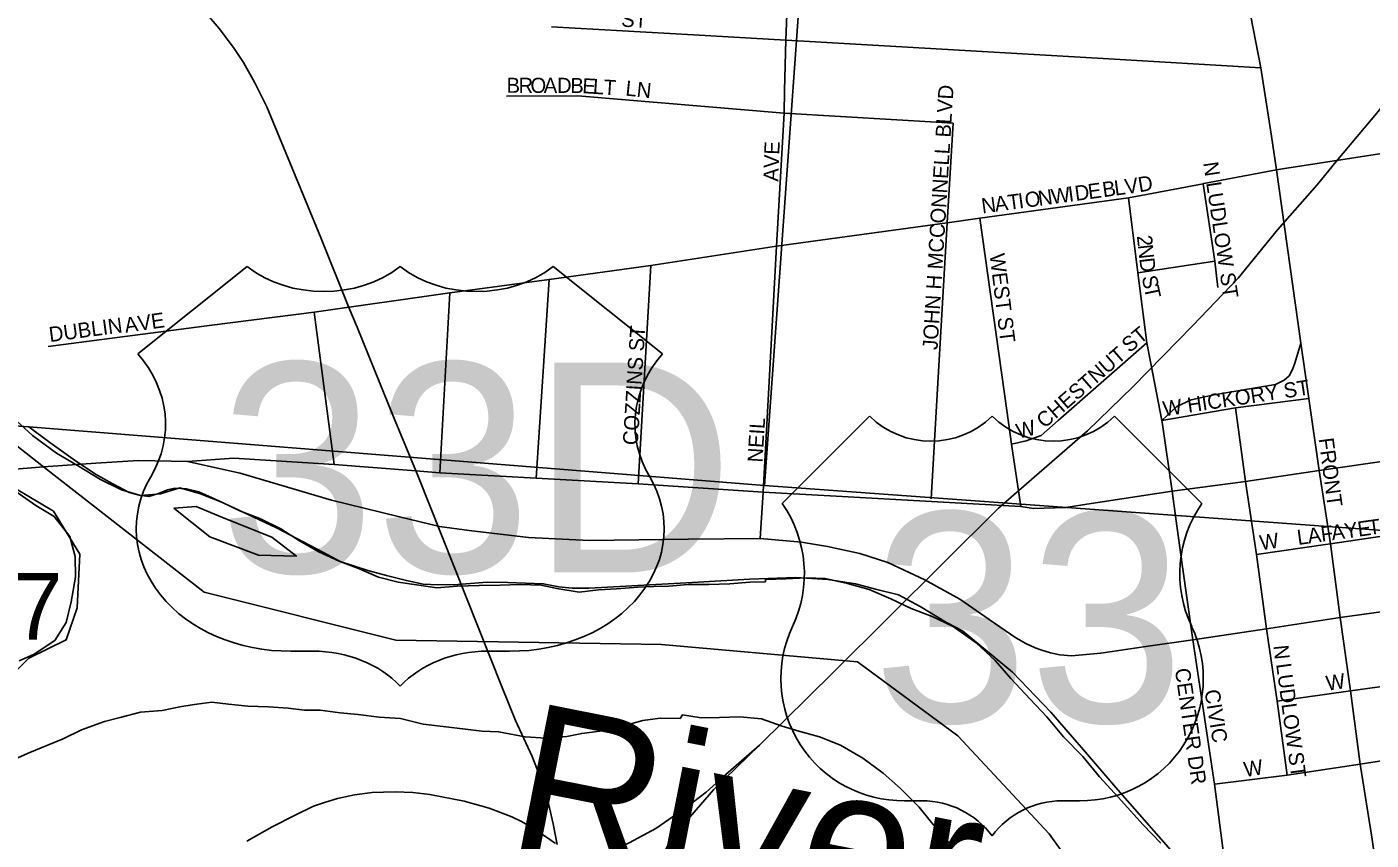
# Model space of a CAD drawing. Extents: x 0 to 34, y -6.2 to 22.
# Drawn here: x 5.72 to 6.564, y 18.089 to 18.6 of the extents above; entities that cross this region are included whole.
import ezdxf

# ---------------------------------------------------------------- set-up
doc = ezdxf.new("R2010")
doc.units = 0
for name, color, linetype in [('GM_X_City_Street', 7, 'Continuous'), ('GM_X_City_Street_Text', 7, 'Continuous'), ('GM_X_Major_River', 7, 'Continuous'), ('GM_X_Major_River_Text', 7, 'Continuous'), ('GM_X_Rail_Line', 7, 'Continuous'), ('GM_X_Section', 7, 'Continuous'), ('GM_X_Section_Text', 7, 'Continuous'), ('GM_X_Township', 7, 'Continuous'), ('GM_X_US_Route', 7, 'Continuous'), ('GM_X_US_Shield', 7, 'Continuous')]:
    doc.layers.add(name, color=color, linetype=linetype)

msp = doc.modelspace()

# ---------------------------------------------------------------- linework, layer by layer
at = {"layer": 'GM_X_City_Street'}
for points in [[(6.19591, 18.56034), (6.19665, 18.59208), (6.20072, 18.6952), (6.20307, 18.75671), (6.20288, 18.76478), (6.1973, 18.78643), (6.19155, 18.79843), (6.17255, 18.82567), (6.16294, 18.83821), (6.15118, 18.86085), (6.1493, 18.86763), (6.13803, 18.94558), (6.12654, 19.0265), (6.11342, 19.1096), (6.10394, 19.17992), (6.09467, 19.24481), (6.08497, 19.31221), (6.07265, 19.3982), (6.06886, 19.42877), (6.06015, 19.48517), (6.05243, 19.53925), (6.03434, 19.65927), (6.03319, 19.66897), (6.01654, 19.78521)], [(6.57176, 18.04339), (6.56472, 18.09113), (6.55749, 18.13701), (6.5515, 18.18306), (6.54503, 18.22919), (6.5388, 18.27541), (6.53176, 18.32162), (6.52531, 18.3669), (6.52024, 18.40154), (6.50489, 18.51058), (6.5018, 18.5316), (6.49515, 18.57457), (6.48857, 18.60785), (6.46909, 18.66011)], [(6.04941, 18.60033), (6.13856, 18.59533)], [(6.13856, 18.59533), (6.19665, 18.59208), (6.20791, 18.59142)], [(6.20791, 18.59142), (6.3961, 18.58038)], [(6.3961, 18.58038), (6.49515, 18.57457)], [(6.02127, 18.5569), (6.06604, 18.55692), (6.19557, 18.54604), (6.30173, 18.53987)], [(6.18061, 18.27874), (6.18232, 18.308), (6.19087, 18.46253), (6.19557, 18.54604), (6.19591, 18.56034)], [(6.29792, 18.47709), (6.30173, 18.53987)], [(6.5087, 18.51116), (6.5981, 18.52495), (6.63218, 18.5294), (6.6614, 18.53335), (6.68411, 18.53354), (6.71024, 18.53311), (6.72321, 18.53176), (6.75566, 18.5262), (6.77652, 18.52249), (6.8361, 18.5132), (6.84154, 18.51287)], [(6.45933, 18.50183), (6.50489, 18.51058), (6.5087, 18.51116)], [(6.41982, 18.49436), (6.4589, 18.50175), (6.45933, 18.50183)], [(6.468, 18.43647), (6.46623, 18.45317), (6.4589, 18.50175)], [(6.19087, 18.46253), (6.29792, 18.47709), (6.3186, 18.48005), (6.41193, 18.49287), (6.41982, 18.49436)], [(6.42346, 18.40188), (6.4179, 18.44584), (6.41193, 18.49287)], [(6.33555, 18.35934), (6.3186, 18.48005)], [(6.28799, 18.3038), (6.29195, 18.37294), (6.29792, 18.47709)], [(5.83605, 18.41279), (5.9003, 18.42112), (5.98565, 18.43319), (6.04796, 18.44167), (6.1119, 18.45035), (6.19087, 18.46253)], [(6.4179, 18.44584), (6.46623, 18.45317)], [(6.10383, 18.3131), (6.1119, 18.45035)], [(6.03972, 18.31672), (6.04796, 18.44167)], [(5.97922, 18.32017), (5.98565, 18.43319)], [(5.9128, 18.32527), (5.9003, 18.42112)], [(5.73319, 18.39946), (5.83605, 18.41279)], [(6.33852, 18.33819), (6.3476, 18.3401), (6.35713, 18.34349), (6.36785, 18.35299), (6.42347, 18.40179)], [(6.43305, 18.35184), (6.43288, 18.35298), (6.42347, 18.40179), (6.42346, 18.40188)], [(6.52024, 18.40154), (6.51642, 18.38894), (6.51504, 18.38499), (6.51287, 18.38105), (6.50971, 18.37828), (6.50439, 18.37552), (6.46552, 18.36901), (6.458, 18.36744)], [(6.458, 18.36744), (6.45132, 18.36605), (6.44224, 18.36171), (6.43288, 18.35298)], [(6.43288, 18.35298), (6.47913, 18.36084), (6.52531, 18.3669)], [(6.51159, 18.13017), (6.50531, 18.17665), (6.49857, 18.22202), (6.49227, 18.26884), (6.48553, 18.31471), (6.47913, 18.36084)], [(6.34428, 18.29902), (6.33852, 18.33819), (6.33555, 18.35934)], [(6.44177, 18.29132), (6.43938, 18.30866), (6.43305, 18.35184)], [(6.47177, 18.07944), (6.46597, 18.12433), (6.45232, 18.21508), (6.44574, 18.26243), (6.44177, 18.29132)], [(6.53564, 18.27497), (6.5388, 18.27541), (6.58532, 18.28232), (6.63316, 18.28922)], [(6.49227, 18.26884), (6.53564, 18.27497)], [(7.16179, 18.22335), (7.16128, 18.22326), (7.10093, 18.2142), (7.0431, 18.2053), (6.98365, 18.19789), (6.93221, 18.19042), (6.88585, 18.18367), (6.83933, 18.1771), (6.79329, 18.17102), (6.70008, 18.1572), (6.65161, 18.15162), (6.60426, 18.14435), (6.55749, 18.13701), (6.51159, 18.13017), (6.46597, 18.12433)], [(6.50531, 18.17665), (6.5515, 18.18306), (6.59853, 18.18947), (6.64653, 18.19605)]]:
    msp.add_lwpolyline(points, dxfattribs=at)
at = {"layer": 'GM_X_Major_River'}
for points in [[(6.18386, 18.25161), (6.17401, 18.25129), (6.1615, 18.25022), (6.14824, 18.24993), (6.13536, 18.25), (6.12323, 18.24893), (6.11376, 18.24861), (6.1039, 18.24829), (6.09026, 18.24723), (6.07889, 18.24654), (6.06676, 18.24509), (6.05276, 18.24745), (6.04292, 18.24941), (6.03004, 18.24986), (6.01716, 18.24956), (6.0039, 18.24926), (5.99026, 18.24896), (5.97737, 18.2479), (5.96602, 18.24948), (5.95315, 18.25145), (5.94066, 18.25456), (5.92819, 18.25995), (5.9161, 18.26458), (5.90325, 18.27034), (5.89117, 18.27725), (5.87947, 18.2849), (5.86625, 18.29143), (5.85416, 18.29606), (5.84282, 18.30144), (5.82884, 18.30683), (5.81598, 18.3107), (5.80384, 18.30698), (5.79133, 18.30591), (5.77923, 18.3094), (5.766, 18.31593), (5.75166, 18.32474), (5.73845, 18.33241), (5.72336, 18.3435), (5.71093, 18.35496)], [(5.71292, 18.30827), (5.72537, 18.29947), (5.73707, 18.29257), (5.74685, 18.27999), (5.75018, 18.26745), (5.75049, 18.25454), (5.74774, 18.239), (5.74463, 18.22612), (5.73737, 18.21478), (5.72444, 18.20612), (5.71494, 18.20201)], [(5.88922, 18.26777), (5.87376, 18.27962), (5.84277, 18.29195), (5.82614, 18.29888), (5.81212, 18.29782)], [(5.81212, 18.29782), (5.83474, 18.27985), (5.86536, 18.26829), (5.88922, 18.26777)], [(6.43216, 18.08735), (6.42124, 18.0988), (6.40543, 18.11635), (6.39376, 18.12894), (6.38323, 18.1419), (6.37118, 18.15412), (6.36065, 18.16671), (6.35011, 18.17777), (6.33806, 18.19075), (6.32828, 18.20219), (6.31622, 18.21326), (6.30189, 18.22359), (6.28866, 18.22974), (6.27544, 18.23475), (6.26259, 18.2409), (6.24899, 18.24668), (6.23537, 18.25055), (6.22138, 18.25367), (6.20963, 18.25412), (6.19675, 18.25343), (6.18387, 18.25313), (6.18386, 18.25161)], [(5.71078, 18.13942), (5.7218, 18.14429), (5.73243, 18.14878), (5.74268, 18.15289), (5.75408, 18.15852), (5.76851, 18.16374), (5.77838, 18.16634), (5.79127, 18.16968), (5.80492, 18.17074), (5.81706, 18.17332), (5.82654, 18.17479), (5.83601, 18.17587), (5.84661, 18.17467), (5.85873, 18.17346), (5.87161, 18.173), (5.8841, 18.17217), (5.89433, 18.17097), (5.90418, 18.17091), (5.91667, 18.16932), (5.92802, 18.16811), (5.94127, 18.16652), (5.95453, 18.16568), (5.96891, 18.16218), (5.9814, 18.16059), (5.99541, 18.15899), (6.00563, 18.15779), (6.01623, 18.15735), (6.03288, 18.15422), (6.04613, 18.15338), (6.05902, 18.15444), (6.0685, 18.15628), (6.08291, 18.1581), (6.09315, 18.16069), (6.10681, 18.16441), (6.11781, 18.16586), (6.13031, 18.16579)], [(6.13031, 18.16579), (6.13184, 18.16805), (6.14357, 18.16609), (6.15494, 18.1664), (6.16782, 18.1667), (6.18145, 18.16548), (6.1943, 18.16085), (6.20489, 18.15776), (6.21775, 18.15426), (6.23098, 18.14887), (6.24495, 18.14082), (6.25777, 18.13126), (6.2687, 18.12171), (6.28038, 18.10988), (6.28827, 18.10034), (6.29918, 18.08737)]]:
    msp.add_lwpolyline(points, dxfattribs=at)
at = {"layer": 'GM_X_Rail_Line'}
for points in [[(5.96546, 18.31843), (5.95021, 18.3553), (5.93797, 18.38526), (5.92732, 18.41165), (5.92215, 18.42405), (5.90467, 18.46736), (5.88504, 18.51504), (5.87463, 18.54039), (5.87058, 18.55009), (5.86316, 18.56513), (5.85584, 18.57796), (5.84958, 18.58747), (5.84067, 18.59932), (5.82965, 18.61223), (5.81901, 18.62303), (5.8061, 18.63435), (5.80036, 18.6394), (5.79244, 18.64522), (5.78255, 18.65163), (5.77138, 18.65843), (5.76428, 18.66235), (5.75802, 18.66537), (5.73175, 18.67584)], [(6.33031, 18.29784), (6.38618, 18.34657), (6.41461, 18.37414), (6.4524, 18.41277), (6.48089, 18.44243), (6.50555, 18.4728), (6.53041, 18.50109), (6.54241, 18.51577), (6.56883, 18.54706), (6.58989, 18.5737)], [(6.053, 18.08653), (6.0505, 18.09956), (6.04827, 18.1095), (6.04414, 18.12356), (6.04073, 18.13326), (6.03739, 18.14184), (6.02682, 18.1645), (6.01855, 18.18515), (5.96546, 18.31843)], [(6.18019, 18.14886), (6.22652, 18.19483), (6.33031, 18.29784)], [(6.06685, 18.07371), (6.08075, 18.07929), (6.09821, 18.08754), (6.11504, 18.09658), (6.13336, 18.10935), (6.14659, 18.11943), (6.15729, 18.12905), (6.18019, 18.14886)], [(6.18019, 18.14886), (6.15117, 18.1208), (6.12824, 18.09435), (6.12182, 18.08473), (6.11736, 18.07465), (6.11289, 18.06309), (6.10911, 18.05026), (6.10751, 18.03607), (6.10829, 18.02231), (6.11122, 18.00374), (6.11281, 17.99634)], [(5.85794, 18.08863), (5.87395, 18.09757), (5.8879, 18.10473), (5.89994, 18.11053), (5.90689, 18.11295), (5.91496, 18.11534), (5.92561, 18.11772), (5.93681, 18.11927), (5.94385, 18.11947), (5.95124, 18.11959), (5.96237, 18.11911), (5.97305, 18.11784), (5.99463, 18.11375), (6.01025, 18.10934), (6.02453, 18.10393), (6.03063, 18.10101), (6.03562, 18.09813), (6.04625, 18.09114), (6.05195, 18.0871)]]:
    msp.add_lwpolyline(points, dxfattribs=at)
at = {"layer": 'GM_X_Section'}
for points in [[(6.25432, 19.30018), (6.18322, 18.31219), (5.72103, 18.34896), (5.6843, 18.35147), (5.74527, 19.32804)], [(6.76078, 19.26937), (6.6863, 18.2758), (6.68124, 18.27598), (6.18322, 18.31219), (6.25432, 19.30018), (6.54767, 19.28066)], [(5.6843, 18.35147), (5.71235, 18.31041), (5.73648, 18.29605), (5.75314, 18.26904), (5.75142, 18.23514), (5.74452, 18.21503), (5.72097, 18.20353), (5.71336, 18.19593), (5.70947, 18.19204), (5.68591, 18.18112), (5.67216, 18.14044)]]:
    msp.add_lwpolyline(points, close=True, dxfattribs=at)
msp.add_lwpolyline([(6.48087, 18.03477), (6.40526, 18.12086), (6.38232, 18.14752), (6.3795, 18.15076), (6.36313, 18.1696), (6.33905, 18.19475), (6.30776, 18.22071), (6.29757, 18.22608), (6.28096, 18.23603), (6.26737, 18.24331), (6.25376, 18.2468), (6.24052, 18.2503), (6.22311, 18.25305), (6.20304, 18.25431), (6.17387, 18.25336), (6.14165, 18.25128), (6.09618, 18.24891), (6.07307, 18.24754), (6.06246, 18.2476), (6.05414, 18.24841), (6.0443, 18.25037), (6.02195, 18.25126), (6.00907, 18.25134), (5.9905, 18.24995), (5.978, 18.24964), (5.96891, 18.25008), (5.95832, 18.25242), (5.94584, 18.25552), (5.93412, 18.25863), (5.91672, 18.26442), (5.90578, 18.27017), (5.8767, 18.2855), (5.86197, 18.29241), (5.83818, 18.30354), (5.82798, 18.30815), (5.82003, 18.31009), (5.81284, 18.31051), (5.80829, 18.30941), (5.80183, 18.30679), (5.79652, 18.30531), (5.79046, 18.30611), (5.78403, 18.30766), (5.77346, 18.31341), (5.76289, 18.31916), (5.74893, 18.32871), (5.73423, 18.33904), (5.72103, 18.34896), (6.18322, 18.31219), (6.68124, 18.27598)], dxfattribs=at)
at = {"layer": 'GM_X_Township'}
msp.add_lwpolyline([(6.06109, 17.43356), (6.11583, 17.48557), (6.17331, 17.52116), (6.24173, 17.55127), (6.30742, 17.59781), (6.34272, 17.63472), (6.36763, 17.66076), (6.40595, 17.71277), (6.44369, 17.78328), (6.46342, 17.83046), (6.46069, 17.89341), (6.45521, 17.96731), (6.41724, 18.01645), (6.36215, 18.0932), (6.30468, 18.15478), (6.24173, 18.2013), (6.11856, 18.21225), (5.95161, 18.21497), (5.83118, 18.24507), (5.73028, 18.32395), (5.68064, 18.36275)], dxfattribs=at)
at = {"layer": 'GM_X_US_Route'}
for points in [[(5.66383, 18.31864), (5.68436, 18.32001), (5.73028, 18.32395), (5.76327, 18.32609), (5.7899, 18.32774), (5.82086, 18.32719)], [(5.96428, 18.32132), (5.9128, 18.32527), (5.84983, 18.32938), (5.82086, 18.32719)], [(5.82086, 18.32719), (5.85394, 18.31985), (5.91132, 18.30291), (5.95393, 18.29243), (5.97917, 18.28626), (5.99763, 18.28384), (6.03496, 18.27952), (6.07325, 18.27759), (6.13524, 18.27841), (6.18061, 18.27874), (6.20642, 18.27644), (6.22293, 18.2738), (6.24325, 18.26937), (6.26067, 18.26383), (6.28394, 18.25291), (6.30589, 18.24077), (6.32445, 18.22799)], [(6.61702, 18.33343), (6.57842, 18.32835), (6.53176, 18.32162), (6.48553, 18.31471), (6.43938, 18.30866), (6.38573, 18.30034)], [(6.22443, 18.30566), (6.18232, 18.308), (6.10383, 18.3131), (6.03972, 18.31672), (5.97922, 18.32017), (5.96428, 18.32132)], [(6.38573, 18.30034), (6.37264, 18.2983), (6.35225, 18.29765), (6.34428, 18.29902), (6.22443, 18.30566)], [(6.54503, 18.22919), (6.5919, 18.23563), (6.63925, 18.2427)], [(6.32445, 18.22799), (6.34123, 18.21643), (6.34748, 18.21282), (6.3534, 18.21002), (6.35685, 18.20887), (6.36294, 18.20706), (6.36885, 18.20574), (6.37609, 18.20509), (6.39466, 18.20673), (6.42278, 18.21085), (6.45232, 18.21508)], [(6.45232, 18.21508), (6.49857, 18.22202), (6.54503, 18.22919)]]:
    msp.add_lwpolyline(points, dxfattribs=at)
at = {"layer": 'GM_X_US_Shield'}
for p, q in [((5.85827, 18.44971), (5.78961, 18.39478)), ((6.1192, 18.39478), (6.05053, 18.44971)), ((6.24933, 18.35565), (6.1944, 18.30072)), ((6.45807, 18.30072), (6.40314, 18.35565)), ((5.88574, 18.20801), (5.89947, 18.20801)), ((6.00933, 18.20801), (6.02307, 18.20801)), ((6.27131, 18.11395), (6.28229, 18.11395)), ((6.37018, 18.11395), (6.38117, 18.11395))]:
    msp.add_line(p, q, dxfattribs=at)
for centre, radius, start, end in [((6.28779, 18.39488), 0.05493, 225.573, 314.427), ((6.36469, 18.39488), 0.05493, 225.573, 314.427), ((6.13141, 18.25661), 0.0769, 334.54712, 35.00093), ((6.52107, 18.25661), 0.0769, 144.99907, 205.45288), ((6.27045, 18.19085), 0.0769, 154.83192, 270.63826), ((6.38203, 18.19085), 0.0769, 269.36174, 25.16808), ((6.28229, 18.05902), 0.05493, 36.8699, 90), ((6.37018, 18.05902), 0.05493, 90, 143.1301)]:
    msp.add_arc(centre, radius, start, end, dxfattribs=at)
for centre, major_axis, start_param, end_param in [((5.90634, 18.48894), (-0.06866, 0), 0.795399, 2.346194), ((6.00247, 18.48894), (-0.06866, 0), 0.795399, 2.346194), ((5.71086, 18.35067), (0.09613, 0), 5.838949, 6.894067), ((6.19794, 18.35067), (-0.09613, 0), 5.672304, 6.727422), ((5.88467, 18.28491), (0.09613, 0), 2.702327, 4.723529), ((6.02414, 18.28491), (-0.09613, 0), 1.559657, 3.580859), ((5.89947, 18.15308), (-0.06866, 0), 3.785094, 4.712389), ((6.00933, 18.15308), (-0.06866, 0), 4.712389, 5.639684)]:
    msp.add_ellipse(centre, major_axis=major_axis, ratio=0.8, start_param=start_param, end_param=end_param, dxfattribs=at)

# ---------------------------------------------------------------- texts
at = {"layer": 'GM_X_City_Street_Text'}
for s, height, rotation, p in [('ST', 0.00947, 356.42622, (6.09302, 18.60056)), ('B', 0.00947, 359.97571, (6.02124, 18.5589)), ('R', 0.00947, 359.97032, (6.02874, 18.55889)), ('O', 0.00947, 359.98126, (6.03624, 18.55889)), ('A', 0.00947, 359.97814, (6.04457, 18.55889)), ('D', 0.00947, 359.97814, (6.0529, 18.55888)), ('B', 0.00947, 358.61584, (6.06118, 18.55888)), ('E', 0.00947, 356.52764, (6.06858, 18.55871)), ('L', 0.00947, 356.20046, (6.07522, 18.5583)), ('T', 0.00947, 356.17138, (6.08188, 18.55786)), ('LN', 0.00947, 353.98201, (6.09559, 18.55722)), ('JOHN H MCCONNELL BLVD', 0.0094697, 86.50314, (6.29196, 18.39718)), ('AVE', 0.00947, 88.02635, (6.19196, 18.50301)), ('N LUDLOW ST', 0.0094697, 278.56056, (6.45884, 18.51487)), ('B', 0.00947, 7.64921, (6.39615, 18.49328)), ('L', 0.00947, 7.67383, (6.40359, 18.49427)), ('V', 0.00947, 7.94126, (6.41025, 18.49517)), ('D', 0.00947, 9.75183, (6.41882, 18.49637)), ('T', 0.00947, 7.662, (6.33669, 18.48527)), ('I', 0.00947, 7.66598, (6.3433, 18.48616)), ('O', 0.00947, 7.65097, (6.34742, 18.48672)), ('N', 0.00947, 7.66735, (6.35569, 18.48783)), ('W', 0.00947, 7.67353, (6.36395, 18.48894)), ('I', 0.00947, 7.67263, (6.37468, 18.49039)), ('D', 0.00947, 7.65097, (6.37881, 18.49094)), ('E', 0.00947, 7.662, (6.38707, 18.49205)), ('N', 0.00947, 7.67263, (6.32017, 18.48305)), ('A', 0.00947, 7.65097, (6.32843, 18.48416)), ('2', 0.00947, 276.19536, (6.41718, 18.46897)), ('N', 0.00947, 276.17606, (6.41781, 18.46317)), ('WEST ST', 0.00947, 277.00088, (6.32467, 18.45733)), ('D', 0.00947, 276.82346, (6.41872, 18.45477)), ('S', 0.00947, 281.36828, (6.42026, 18.44322)), ('T', 0.00947, 281.91008, (6.42159, 18.43659)), ('AVE', 0.00947, 8.12573, (5.78182, 18.40805)), ('DUBLIN', 0.00947, 7.66649, (5.73433, 18.40222)), ('COZZINS ST', 0.00947, 86.33138, (6.10363, 18.33723)), ('ST', 0.00947, 39.80736, (6.4126, 18.39515)), ('CHESTNUT', 0.00947, 41.11303, (6.3592, 18.3476)), ('W HICKORY ST', 0.0094697, 8.52959, (6.4343, 18.35555)), ('NEIL', 0.00947, 86.42578, (6.18196, 18.32639)), ('W', 0.00947, 14.66826, (6.34284, 18.34142)), ('FRONT', 0.00947, 277.59497, (6.53134, 18.34152)), ('L', 0.00947, 7.83652, (6.5185, 18.27471)), ('A', 0.00947, 7.83948, (6.5251, 18.27562)), ('F', 0.00947, 7.83652, (6.53336, 18.27676)), ('A', 0.00947, 7.83948, (6.53996, 18.27767)), ('Y', 0.00947, 7.82718, (6.54822, 18.27881)), ('E', 0.00947, 7.85016, (6.55648, 18.27994)), ('T', 0.00947, 7.83652, (6.56308, 18.28086)), ('W', 0.00947, 8.74111, (6.49514, 18.27138)), ('N', 0.00947, 275.70844, (6.50301, 18.21146)), ('LUDLOW', 0.00947, 277.59393, (6.50467, 18.19985)), ('CENTER DR', 0.00947, 278.23678, (6.44105, 18.1967)), ('W', 0.00947, 8.74111, (6.5368, 18.18304)), ('CIVIC', 0.00947, 278.97382, (6.45967, 18.18323)), ('ST', 0.00947, 277.60515, (6.51217, 18.14402)), ('W', 0.00947, 8.74111, (6.48513, 18.12888))]:
    msp.add_text(s, height=height, rotation=rotation, dxfattribs=at).set_placement(p)
at = {"layer": 'GM_X_Major_River_Text'}
msp.add_text('River', height=0.094694, rotation=348.77331, dxfattribs=at).set_placement((6.01962, 18.0835))
at = {"layer": 'GM_X_Section_Text'}
msp.add_text('17', height=0.041856, rotation=0.00001, dxfattribs=at).set_placement((5.67999, 18.2152))
at = {"layer": 'GM_X_US_Shield'}
for s, p in [('33D', (5.84069, 18.25745)), ('33', (6.2512, 18.16339))]:
    msp.add_text(s, height=0.131836, dxfattribs=at).set_placement(p)

doc.saveas('drawing.dxf')
